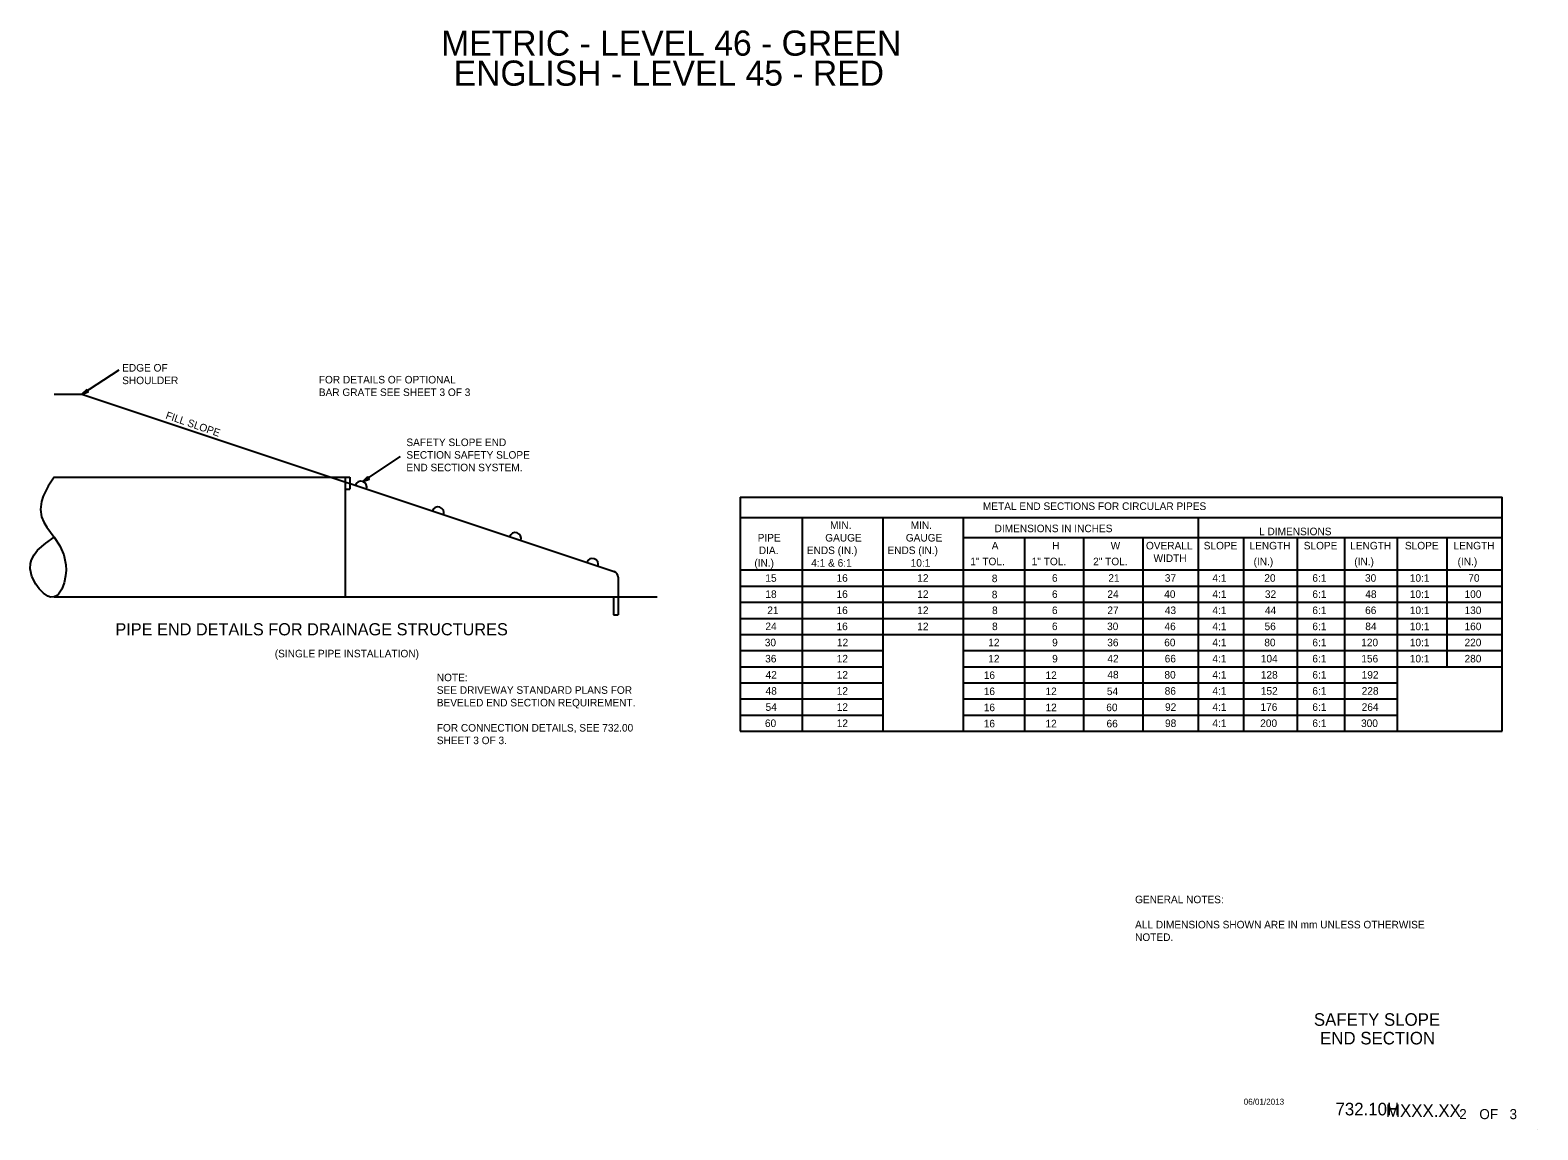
# Model space of a CAD drawing. Extents: x -437.8 to -407.9, y -458.1 to -436.2.
import ezdxf

# ---------------------------------------------------------------- set-up
doc = ezdxf.new("R2010")
doc.units = 0
for name, color, linetype in [('Border-Full plan shape', 7, 'Continuous'), ('Border-Plotting block', 7, 'Continuous'), ('Default', 7, 'Continuous'), ('Level 46', 7, 'Continuous')]:
    doc.layers.add(name, color=color, linetype=linetype)

msp = doc.modelspace()

# ---------------------------------------------------------------- linework, layer by layer
at = {"layer": 'Border-Plotting block'}
msp.add_line((-407.859, -458.051), (-407.859, -458.051), dxfattribs=at)
msp.add_line((-407.859, -458.051), (-407.859, -458.051), dxfattribs=at)
msp.add_line((-407.859, -458.051), (-407.859, -458.051), dxfattribs=at)
msp.add_line((-407.859, -458.051), (-407.859, -458.051), dxfattribs=at)
msp.add_line((-407.859, -458.051), (-407.859, -458.051), dxfattribs=at)
msp.add_line((-407.859, -458.051), (-407.859, -458.051), dxfattribs=at)
msp.add_line((-407.859, -458.051), (-407.859, -458.051), dxfattribs=at)
msp.add_line((-407.859, -458.051), (-407.859, -458.051), dxfattribs=at)
at = {"layer": 'Default'}
for p, q in [((-436.777, -443.434), (-436.041, -442.949)), ((-437.326, -443.434), (-436.777, -443.434)), ((-436.777, -443.434), (-426.207, -446.958)), ((-431.2, -445.168), (-430.448, -444.673)), ((-437.326, -445.081), (-431.455, -445.081)), ((-431.551, -445.081), (-431.551, -447.463)), ((-431.455, -445.081), (-431.455, -445.319)), ((-431.551, -445.319), (-431.455, -445.319)), ((-423.7, -445.479), (-408.57, -445.479)), ((-423.7, -445.479), (-423.7, -450.13)), ((-408.57, -450.13), (-408.57, -445.479)), ((-423.7, -445.879), (-408.573, -445.879)), ((-422.466, -450.13), (-422.466, -445.879)), ((-420.866, -450.13), (-420.866, -445.879)), ((-419.266, -450.13), (-419.266, -445.879)), ((-414.597, -450.13), (-414.597, -445.879)), ((-419.266, -446.281), (-408.573, -446.281)), ((-418.046, -450.13), (-418.046, -446.281)), ((-416.879, -450.13), (-416.879, -446.281)), ((-415.701, -450.13), (-415.701, -446.281)), ((-413.701, -450.13), (-413.701, -446.281)), ((-412.634, -450.13), (-412.634, -446.281)), ((-411.691, -450.13), (-411.691, -446.281)), ((-410.644, -450.13), (-410.644, -446.281)), ((-409.66, -448.848), (-409.66, -446.281)), ((-426.126, -447.07), (-426.126, -447.817)), ((-423.7, -446.924), (-408.57, -446.924)), ((-423.7, -447.244), (-408.57, -447.244)), ((-437.326, -447.461), (-425.354, -447.461)), ((-426.22, -447.461), (-426.22, -447.817)), ((-423.7, -447.565), (-408.57, -447.565)), ((-426.22, -447.817), (-426.126, -447.817)), ((-423.7, -447.886), (-408.57, -447.886)), ((-423.7, -448.206), (-408.57, -448.206)), ((-423.7, -448.527), (-420.866, -448.527)), ((-419.266, -448.527), (-408.57, -448.527)), ((-423.7, -448.848), (-420.866, -448.848)), ((-419.266, -448.848), (-408.57, -448.848)), ((-423.7, -449.169), (-420.866, -449.169)), ((-419.266, -449.169), (-410.644, -449.169)), ((-423.7, -449.488), (-420.866, -449.488)), ((-419.266, -449.488), (-410.644, -449.488)), ((-423.7, -449.809), (-420.866, -449.809)), ((-419.266, -449.809), (-410.644, -449.809)), ((-423.7, -450.13), (-408.57, -450.13))]:
    msp.add_line(p, q, dxfattribs=at)
for points in [[(-436.681, -443.337), (-436.777, -443.434), (-436.651, -443.384)], [(-431.103, -445.071), (-431.2, -445.168), (-431.073, -445.117)]]:
    msp.add_lwpolyline(points, close=True, dxfattribs=at)
msp.add_lwpolyline([(-437.326, -445.081), (-437.451, -445.259), (-437.547, -445.461), (-437.579, -445.565), (-437.599, -445.722), (-437.58, -445.871), (-437.536, -445.976), (-437.474, -446.076), (-437.326, -446.271), (-437.216, -446.442), (-437.135, -446.625), (-437.094, -446.824), (-437.091, -446.93), (-437.101, -447.042), (-437.13, -447.178), (-437.179, -447.305), (-437.245, -447.405), (-437.284, -447.44), (-437.326, -447.46), (-437.399, -447.463), (-437.457, -447.444), (-437.544, -447.386), (-437.628, -447.302), (-437.695, -447.21), (-437.77, -447.057), (-437.806, -446.901), (-437.8, -446.797), (-437.78, -446.724), (-437.728, -446.623), (-437.657, -446.531), (-437.497, -446.389), (-437.326, -446.271)], dxfattribs=at)
for centre, start, end in [((-431.237, -445.281), 341.5668, 161.565), ((-429.705, -445.791), 341.567, 161.5652), ((-428.172, -446.302), 341.5684, 161.5659), ((-426.639, -446.813), 341.5678, 161.5623), ((-426.245, -447.07), 0, 71.5649)]:
    msp.add_arc(centre, 0.119, start, end, dxfattribs=at)

# ---------------------------------------------------------------- texts
at = {"layer": 'Border-Full plan shape'}
for s, height, p in [('ENGLISH - LEVEL 45 - RED', 0.5, (-429.393, -437.301)), ('732.10H', 0.25, (-411.878, -457.763))]:
    msp.add_text(s, height=height, dxfattribs=at).set_placement(p)
at = {"layer": 'Border-Plotting block'}
for s, height, p in [('SAFETY SLOPE', 0.25, (-412.308, -455.983)), ('END SECTION', 0.25, (-412.184, -456.353)), ('06/01/2013', 0.12, (-413.701, -457.552)), ('2', 0.2, (-409.421, -457.838)), ('OF', 0.2, (-409.021, -457.838)), ('3', 0.2, (-408.421, -457.838))]:
    msp.add_text(s, height=height, dxfattribs=at).set_placement(p)
at = {"layer": 'Default'}
for s, height, p in [('EDGE OF ', 0.15, (-435.978, -442.982)), ('SHOULDER', 0.15, (-435.978, -443.232)), ('FOR DETAILS OF OPTIONAL ', 0.15, (-432.072, -443.218)), ('BAR GRATE SEE SHEET 3 OF 3', 0.15, (-432.072, -443.468)), ('SAFETY SLOPE END ', 0.15, (-430.333, -444.463)), ('SECTION SAFETY SLOPE ', 0.15, (-430.333, -444.713)), ('END SECTION SYSTEM.', 0.15, (-430.333, -444.963)), ('METAL END SECTIONS FOR CIRCULAR PIPES', 0.15, (-418.882, -445.732)), ('GAUGE', 0.15, (-422.013, -446.359)), ('MIN.', 0.15, (-421.916, -446.109)), ('GAUGE', 0.15, (-420.413, -446.359)), ('MIN.', 0.15, (-420.316, -446.109)), ('DIMENSIONS IN INCHES', 0.15, (-418.649, -446.174)), ('L DIMENSIONS', 0.15, (-413.396, -446.234)), ('PIPE', 0.15, (-423.355, -446.359)), ('DIA.', 0.15, (-423.333, -446.609)), ('ENDS (IN.)', 0.15, (-422.379, -446.609)), ('ENDS (IN.)', 0.15, (-420.778, -446.609)), ('A', 0.15, (-418.706, -446.516)), ('H', 0.15, (-417.506, -446.516)), ('W', 0.15, (-416.344, -446.516)), ('OVERALL', 0.15, (-415.643, -446.516)), ('SLOPE', 0.15, (-414.496, -446.516)), ('LENGTH', 0.15, (-413.586, -446.516)), ('SLOPE', 0.15, (-412.509, -446.516)), ('LENGTH', 0.15, (-411.586, -446.516)), ('SLOPE', 0.15, (-410.499, -446.516)), ('LENGTH', 0.15, (-409.534, -446.516)), ('(IN.)', 0.15, (-423.421, -446.859)), ('4:1 & 6:1', 0.15, (-422.291, -446.859)), ('10:1', 0.15, (-420.316, -446.859)), ('1" TOL.', 0.15, (-419.131, -446.831)), ('1" TOL.', 0.15, (-417.912, -446.831)), ('2" TOL.', 0.15, (-416.692, -446.831)), ('WIDTH', 0.15, (-415.493, -446.766)), ('(IN.)', 0.15, (-413.505, -446.831)), ('(IN.)', 0.15, (-411.505, -446.831)), ('(IN.)', 0.15, (-409.453, -446.831)), ('15', 0.15, (-423.202, -447.159)), ('16', 0.15, (-421.789, -447.159)), ('12', 0.15, (-420.185, -447.159)), ('8', 0.15, (-418.705, -447.167)), ('6', 0.15, (-417.51, -447.159)), ('21', 0.15, (-416.39, -447.159)), ('37', 0.15, (-415.268, -447.159)), ('4:1', 0.15, (-414.324, -447.159)), ('20', 0.15, (-413.292, -447.159)), ('6:1', 0.15, (-412.338, -447.159)), ('30', 0.15, (-411.292, -447.159)), ('10:1', 0.15, (-410.402, -447.159)), ('70', 0.15, (-409.24, -447.159)), ('18', 0.15, (-423.202, -447.48)), ('16', 0.15, (-421.789, -447.48)), ('12', 0.15, (-420.185, -447.48)), ('8', 0.15, (-418.705, -447.488)), ('6', 0.15, (-417.51, -447.48)), ('24', 0.15, (-416.409, -447.48)), ('40', 0.15, (-415.28, -447.48)), ('4:1', 0.15, (-414.324, -447.48)), ('32', 0.15, (-413.28, -447.48)), ('6:1', 0.15, (-412.338, -447.48)), ('48', 0.15, (-411.286, -447.48)), ('10:1', 0.15, (-410.402, -447.48)), ('100', 0.15, (-409.315, -447.48)), ('21', 0.15, (-423.164, -447.801)), ('16', 0.15, (-421.789, -447.801)), ('12', 0.15, (-420.185, -447.801)), ('8', 0.15, (-418.7, -447.801)), ('6', 0.15, (-417.51, -447.801)), ('27', 0.15, (-416.409, -447.801)), ('43', 0.15, (-415.268, -447.801)), ('4:1', 0.15, (-414.324, -447.801)), ('44', 0.15, (-413.28, -447.801)), ('6:1', 0.15, (-412.338, -447.801)), ('66', 0.15, (-411.29, -447.801)), ('10:1', 0.15, (-410.402, -447.801)), ('130', 0.15, (-409.315, -447.801)), ('PIPE END DETAILS FOR DRAINAGE STRUCTURES', 0.24169, (-436.112, -448.224)), ('24', 0.15, (-423.202, -448.12)), ('16', 0.15, (-421.789, -448.121)), ('12', 0.15, (-420.185, -448.121)), ('8', 0.15, (-418.7, -448.12)), ('6', 0.15, (-417.51, -448.12)), ('30', 0.15, (-416.415, -448.12)), ('46', 0.15, (-415.275, -448.121)), ('4:1', 0.15, (-414.324, -448.121)), ('56', 0.15, (-413.287, -448.121)), ('6:1', 0.15, (-412.338, -448.121)), ('84', 0.15, (-411.286, -448.12)), ('10:1', 0.15, (-410.402, -448.121)), ('160', 0.15, (-409.315, -448.121)), ('30', 0.15, (-423.214, -448.441)), ('12', 0.15, (-421.781, -448.441)), ('12', 0.15, (-418.775, -448.441)), ('9', 0.15, (-417.506, -448.441)), ('36', 0.15, (-416.412, -448.441)), ('60', 0.15, (-415.28, -448.441)), ('4:1', 0.15, (-414.324, -448.441)), ('80', 0.15, (-413.292, -448.441)), ('6:1', 0.15, (-412.338, -448.441)), ('120', 0.15, (-411.367, -448.441)), ('10:1', 0.15, (-410.402, -448.441)), ('220', 0.15, (-409.315, -448.441)), ('(SINGLE PIPE INSTALLATION)', 0.15, (-432.947, -448.661)), ('36', 0.15, (-423.206, -448.762)), ('12', 0.15, (-421.785, -448.762)), ('12', 0.15, (-418.775, -448.762)), ('9', 0.15, (-417.506, -448.762)), ('42', 0.15, (-416.409, -448.762)), ('66', 0.15, (-415.271, -448.762)), ('4:1', 0.15, (-414.324, -448.762)), ('104', 0.15, (-413.361, -448.762)), ('6:1', 0.15, (-412.338, -448.762)), ('156', 0.15, (-411.365, -448.762)), ('10:1', 0.15, (-410.402, -448.762)), ('280', 0.15, (-409.315, -448.762)), ('NOTE:', 0.15, (-429.729, -449.136)), ('42', 0.15, (-423.198, -449.083)), ('12', 0.15, (-421.785, -449.083)), ('16', 0.15, (-418.865, -449.091)), ('12', 0.15, (-417.638, -449.091)), ('48', 0.15, (-416.409, -449.08)), ('80', 0.15, (-415.276, -449.083)), ('4:1', 0.15, (-414.324, -449.083)), ('128', 0.15, (-413.361, -449.083)), ('6:1', 0.15, (-412.338, -449.083)), ('192', 0.15, (-411.358, -449.083)), ('SEE DRIVEWAY STANDARD PLANS FOR ', 0.15, (-429.729, -449.386)), ('BEVELED END SECTION REQUIREMENT.', 0.15, (-429.729, -449.636)), ('48', 0.15, (-423.198, -449.403)), ('12', 0.15, (-421.785, -449.403)), ('16', 0.15, (-418.865, -449.411)), ('12', 0.15, (-417.638, -449.411)), ('54', 0.15, (-416.419, -449.411)), ('86', 0.15, (-415.271, -449.403)), ('4:1', 0.15, (-414.324, -449.403)), ('152', 0.15, (-413.361, -449.403)), ('6:1', 0.15, (-412.338, -449.403)), ('228', 0.15, (-411.358, -449.403)), ('54', 0.15, (-423.198, -449.724)), ('12', 0.15, (-421.785, -449.724)), ('16', 0.15, (-418.865, -449.731)), ('12', 0.15, (-417.638, -449.731)), ('60', 0.15, (-416.431, -449.731)), ('92', 0.15, (-415.264, -449.724)), ('4:1', 0.15, (-414.324, -449.724)), ('176', 0.15, (-413.368, -449.724)), ('6:1', 0.15, (-412.338, -449.724)), ('264', 0.15, (-411.358, -449.724)), ('FOR CONNECTION DETAILS, SEE 732.00', 0.15, (-429.729, -450.136)), ('60', 0.15, (-423.211, -450.045)), ('12', 0.15, (-421.785, -450.045)), ('16', 0.15, (-418.865, -450.052)), ('12', 0.15, (-417.638, -450.052)), ('66', 0.15, (-416.426, -450.052)), ('98', 0.15, (-415.264, -450.045)), ('4:1', 0.15, (-414.324, -450.045)), ('200', 0.15, (-413.373, -450.045)), ('6:1', 0.15, (-412.338, -450.045)), ('300', 0.15, (-411.37, -450.045)), ('SHEET 3 OF 3.', 0.15, (-429.729, -450.386))]:
    msp.add_text(s, height=height, dxfattribs=at).set_placement(p)
msp.add_text('FILL SLOPE', height=0.15, rotation=340.9912, dxfattribs=at).set_placement((-435.128, -443.913))
at = {"layer": 'Level 46'}
for s, height, p in [('METRIC - LEVEL 46 - GREEN', 0.5, (-429.642, -436.705)), ('GENERAL NOTES:', 0.15, (-415.859, -453.547)), ('ALL DIMENSIONS SHOWN ARE IN mm UNLESS OTHERWISE ', 0.15, (-415.859, -454.047)), ('NOTED.', 0.15, (-415.859, -454.297)), ('MXXX.XX', 0.25, (-410.875, -457.792))]:
    msp.add_text(s, height=height, dxfattribs=at).set_placement(p)

doc.saveas('drawing.dxf')
